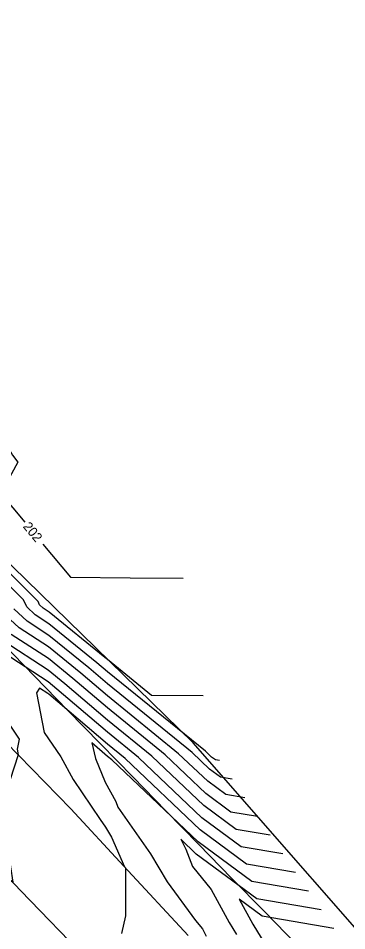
# Model space of a CAD drawing. Extents: x 2086416 to 2115205, y 575507 to 632762.
# Drawn here: x 2110247.4 to 2110316.9, y 582081.1 to 582274.4 of the extents above; entities that cross this region are included whole.
import ezdxf

# ---------------------------------------------------------------- set-up
doc = ezdxf.new("R2010")
doc.units = 0
for name, color, linetype in [('DTM Contours Major', 7, 'Continuous'), ('DTM Contours Minor', 7, 'Continuous'), ('DTM Contours Minor Text', 7, 'Continuous'), ('Exist Hydrographic FEMA Cross Section', 7, 'Continuous'), ('Exist Roads EOP', 7, 'Continuous'), ('Exist Vegetation Woods Line', 7, 'Continuous')]:
    doc.layers.add(name, color=color, linetype=linetype)

msp = doc.modelspace()

# ---------------------------------------------------------------- linework, layer by layer
at = {"layer": 'DTM Contours Major'}
for points in [[(2110290, 582117.14), (2110289.15, 582117.29), (2110288.34, 582117.88), (2110287.04, 582119.12), (2110266.32, 582135.96), (2110264.06, 582137.88), (2110253.94, 582146.12), (2110251, 582148.03), (2110249.23, 582149.7), (2110248.56, 582151.2), (2110232.69, 582167.05), (2110231.99, 582168.26), (2110230.29, 582169.96), (2110225.81, 582174.22), (2110219.47, 582186.28)], [(2110303.45, 582097.38), (2110294.64, 582098.89), (2110286.31, 582105.05), (2110272.88, 582117.83), (2110266.32, 582123.16), (2110255.61, 582132.3), (2110253.76, 582133.81), (2110242.54, 582141.09), (2110239.17, 582144.26), (2110235.48, 582144.01), (2110235.12, 582143.67), (2110240.07, 582132.89), (2110241.85, 582130.25)], [(2110245.21, 582125.28), (2110247.64, 582121.68), (2110247.24, 582119.54), (2110247.42, 582118.38), (2110244.01, 582107.89), (2110243.92, 582107.4), (2110244.29, 582104.39), (2110246.27, 582091.41), (2110242.5, 582092.91), (2110237.49, 582094.05), (2110233.41, 582097.47), (2110224, 582105.68), (2110218.29, 582109.52), (2110211.34, 582115.8), (2110211.3, 582115.8), (2110211.29, 582115.81), (2110211.29, 582115.84), (2110204.27, 582122.09), (2110196.34, 582130.95)]]:
    msp.add_lwpolyline(points, dxfattribs=at)
at = {"layer": 'DTM Contours Minor'}
for points in [[(2110235.58, 582200.71), (2110237.04, 582198.16), (2110246.25, 582181.86), (2110247.35, 582180.34), (2110243.79, 582173.72), (2110248.85, 582167.62)], [(2110286.6, 582130.83), (2110275.64, 582130.94), (2110266.32, 582138.52), (2110265.75, 582139), (2110253.98, 582148.59), (2110252.69, 582149.42), (2110251.92, 582150.15), (2110251.63, 582150.81), (2110232.67, 582169.74)], [(2110252.68, 582163), (2110258.47, 582156), (2110271.1, 582155.87), (2110282.37, 582155.76)], [(2110295.38, 582109.24), (2110291.34, 582109.93), (2110287.53, 582112.75), (2110281.38, 582118.6), (2110266.32, 582130.84), (2110260.68, 582135.65), (2110253.87, 582141.2), (2110247.62, 582145.26), (2110243.85, 582148.79)], [(2110292.69, 582113.19), (2110290.24, 582113.61), (2110287.93, 582115.32), (2110284.21, 582118.86), (2110266.32, 582133.4), (2110262.37, 582136.77), (2110253.91, 582143.66), (2110249.31, 582146.65), (2110246.54, 582149.25)], [(2110298.07, 582105.29), (2110292.44, 582106.25), (2110287.12, 582110.18), (2110278.54, 582118.34), (2110266.32, 582128.28), (2110258.99, 582134.53), (2110253.83, 582138.74), (2110245.92, 582143.87)], [(2110300.76, 582101.34), (2110293.54, 582102.57), (2110286.71, 582107.62), (2110275.71, 582118.09), (2110266.32, 582125.72), (2110257.3, 582133.42), (2110253.79, 582136.27), (2110244.23, 582142.48)], [(2110306.13, 582093.43), (2110295.73, 582095.21), (2110285.9, 582102.48), (2110270.05, 582117.57), (2110266.32, 582120.6), (2110253.92, 582131.18), (2110253.72, 582131.35), (2110251.95, 582132.49), (2110251.31, 582131.47), (2110252.95, 582123.09), (2110256.44, 582117.95), (2110259.04, 582113.13), (2110264.79, 582104.69), (2110265.93, 582103.07), (2110267.2, 582100.94), (2110269.96, 582094.66), (2110270.11, 582094.43), (2110270.15, 582084.25), (2110269.26, 582080.53)], [(2110308.82, 582089.48), (2110296.83, 582091.53), (2110285.49, 582099.92), (2110267.22, 582117.31), (2110266.32, 582118.04), (2110262.99, 582120.89), (2110263.79, 582117.57), (2110265.83, 582112.58), (2110268.06, 582108.45), (2110268.5, 582107.27), (2110275.42, 582097.4), (2110278.98, 582091.44), (2110284.96, 582083.29), (2110286.44, 582081.48), (2110287.22, 582079.93)], [(2110311.51, 582085.53), (2110297.93, 582087.85), (2110285.08, 582097.35), (2110281.81, 582100.47), (2110282.92, 582098.41), (2110284.3, 582094.72), (2110288.25, 582089.85), (2110292.08, 582082.87), (2110293.64, 582080.28)], [(2110314.2, 582081.58), (2110299.03, 582084.17), (2110294.18, 582087.76), (2110297.06, 582082.5), (2110300.58, 582076.68)]]:
    msp.add_lwpolyline(points, dxfattribs=at)
at = {"layer": 'Exist Hydrographic FEMA Cross Section'}
msp.add_lwpolyline([(2110306.46, 582078.04), (2110299.52, 582085.15), (2110292.58, 582092.26), (2110285.65, 582099.37), (2110278.7, 582106.49), (2110271.77, 582113.6), (2110264.83, 582120.71), (2110257.89, 582127.82), (2110250.95, 582134.94), (2110244.01, 582142.05)], dxfattribs=at)
at = {"layer": 'Exist Roads EOP'}
for points in [[(2110283.42, 582080.08), (2110269.79, 582094.77), (2110258.57, 582106.89), (2110244.84, 582121.04), (2110232.61, 582133.97), (2110220.43, 582147.01), (2110205.56, 582162.74), (2110193.7, 582175.26), (2110182.38, 582187.32), (2110170.57, 582200.14), (2110157.55, 582213.9), (2110148.13, 582223.91), (2110139.67, 582233.18), (2110129.17, 582244.2), (2110118.25, 582256.11), (2110105.57, 582269.53), (2110093.37, 582282.59), (2110082.14, 582294.76), (2110071.88, 582305.53), (2110059.32, 582319.17)], [(2110044.03, 582306.54), (2110057.72, 582292.25), (2110067.42, 582282.08), (2110077.05, 582271.73), (2110082.67, 582265.54), (2110091.18, 582256.81), (2110101.9, 582244.92), (2110112.61, 582233.51), (2110124.83, 582220.15), (2110138.66, 582205.71), (2110150.44, 582192.87), (2110163.31, 582179.2), (2110176.51, 582165.18), (2110187.09, 582154.1), (2110200.16, 582140.29), (2110212.15, 582128.06), (2110221.2, 582117.92), (2110235.62, 582102.6), (2110247.94, 582089.65), (2110262.41, 582074.68), (2110272.71, 582063.48), (2110283.25, 582052.48)]]:
    msp.add_lwpolyline(points, dxfattribs=at)
at = {"layer": 'Exist Vegetation Woods Line'}
for points in [[(2110284.48, 582120.87), (2110225.58, 582178.38), (2110175.08, 582234.49), (2110136.61, 582281.24), (2110106.48, 582313.41), (2110078.56, 582339.36)], [(2111059.79, 581657.65), (2110968.73, 581672.25), (2110864.06, 581705.25), (2110784.73, 581740.8), (2110702.3, 581784.67), (2110632.54, 581823.34), (2110568.48, 581865.95), (2110498.27, 581913.79), (2110441.66, 581966.78), (2110387.94, 582016.39), (2110334.43, 582063.69), (2110284.48, 582120.87)]]:
    msp.add_lwpolyline(points, dxfattribs=at)

# ---------------------------------------------------------------- texts
at = {"layer": 'DTM Contours Minor Text'}
msp.add_text('202', height=2, rotation=309.6491, dxfattribs=at).set_placement((2110248.33, 582166.67))

doc.saveas('drawing.dxf')
